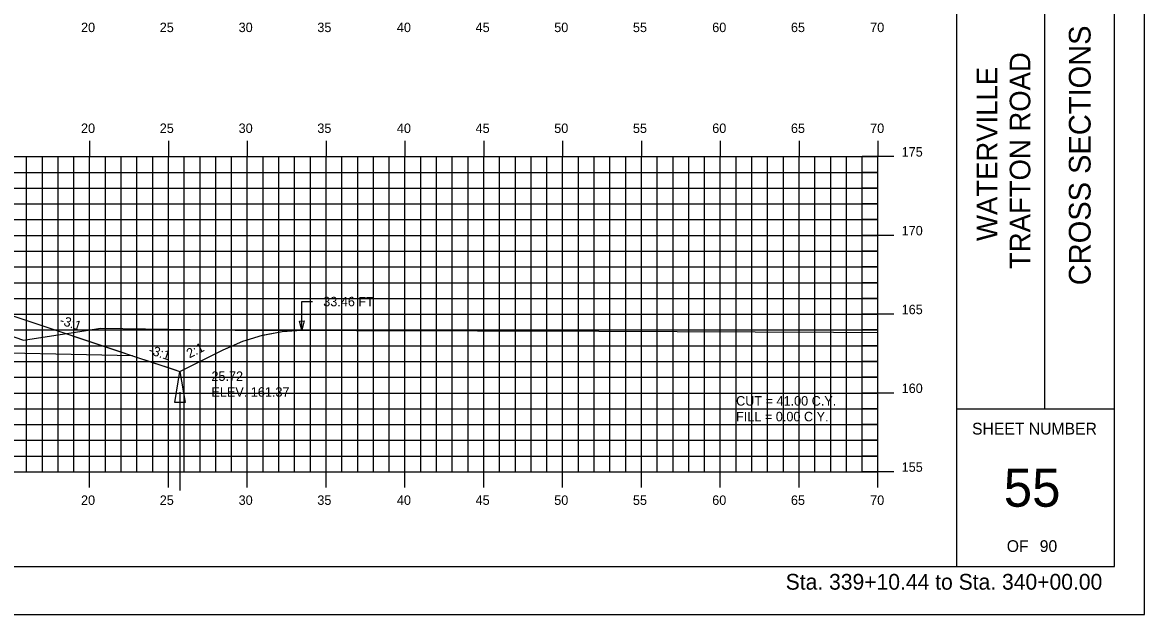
# Model space of a CAD drawing. Extents: x 1142755 to 1142925, y 608981 to 609091.
# Drawn here: x 1142853.5 to 1142924.7, y 608981.3 to 609018.8 of the extents above; entities that cross this region are included whole.
import ezdxf

# ---------------------------------------------------------------- set-up
doc = ezdxf.new("R2010")
doc.units = 0
for name, color, linetype in [('ANNOTATION', 7, 'Continuous'), ('BORDER', 7, 'Continuous'), ('D_Drainage_Ditch_Line', 7, 'Continuous'), ('D_Roadway_SlopeLines', 7, 'Continuous'), ('D_Roadway_SubGrade', 7, 'Continuous'), ('D_Text_Standard', 7, 'Continuous'), ('H_V ANNOTATION', 7, 'Continuous'), ('HIGHWAY_TITLE', 7, 'Continuous'), ('MAJOR', 7, 'Continuous'), ('MINOR', 7, 'Continuous'), ('PLOT BOUNDARY', 7, 'Continuous'), ('S_Roadway_Centerline', 7, 'Continuous')]:
    doc.layers.add(name, color=color, linetype=linetype)

msp = doc.modelspace()

# ---------------------------------------------------------------- linework, layer by layer
msp.add_lwpolyline([(1142852.81, 609000.277), (1142859.606, 608998.012), (1142860.533, 608997.703), (1142863.173, 608996.823), (1142863.533, 608996.703), (1142863.862, 608996.867), (1142866.272, 608998.072), (1142866.422, 608998.137), (1142867.522, 608998.618), (1142867.672, 608998.665), (1142868.772, 608999.007), (1142868.922, 608999.035), (1142870.022, 608999.239), (1142870.172, 608999.248), (1142871.272, 608999.314)])
at = {"layer": 'BORDER'}
for p, q in [((1142912.81, 608984.335), (1142912.81, 609089.335)), ((1142918.401, 608994.338), (1142918.401, 609029.338)), ((1142912.81, 608994.338), (1142922.81, 608994.338))]:
    msp.add_line(p, q, dxfattribs=at)
msp.add_lwpolyline([(1142762.81, 608984.335), (1142922.81, 608984.335), (1142922.81, 609089.335), (1142762.81, 609089.335)], close=True, dxfattribs=at)
at = {"layer": 'D_Drainage_Ditch_Line'}
msp.add_line((1142863.534, 608995.39), (1142863.533, 608989.147), dxfattribs=at)
msp.add_lwpolyline([(1142863.862, 608994.734), (1142863.205, 608994.734), (1142863.533, 608996.703)], close=True, dxfattribs=at)
at = {"layer": 'D_Roadway_SlopeLines'}
for points in [[(1142863.533, 608996.703), (1142866.272, 608998.072), (1142867.522, 608998.618), (1142868.772, 608999.007), (1142870.022, 608999.239), (1142871.272, 608999.314)], [(1142860.533, 608997.703), (1142863.533, 608996.703)]]:
    msp.add_lwpolyline(points, dxfattribs=at)
at = {"layer": 'D_Roadway_SubGrade'}
msp.add_lwpolyline([(1142848.81, 609000.021), (1142848.81, 609000.187), (1142852.81, 609000.027), (1142852.81, 609000.277), (1142852.81, 609000.277), (1142860.533, 608997.703), (1142848.81, 608997.937)], close=True, dxfattribs=at)
at = {"layer": 'D_Text_Standard'}
msp.add_lwpolyline([(1142871.272, 608999.322), (1142871.265, 609001.136), (1142871.945, 609001.136)], dxfattribs=at)
msp.add_lwpolyline([(1142871.272, 608999.322), (1142871.124, 608999.903), (1142871.415, 608999.904)], close=True, dxfattribs=at)
at = {"layer": 'MAJOR'}
for p, q in [((1142857.81, 609011.337), (1142857.81, 609010.335)), ((1142862.81, 609011.337), (1142862.81, 609010.335)), ((1142867.81, 609011.337), (1142867.81, 609010.335)), ((1142872.81, 609011.337), (1142872.81, 609010.335)), ((1142877.81, 609011.337), (1142877.81, 609010.335)), ((1142882.81, 609011.337), (1142882.81, 609010.335)), ((1142887.81, 609011.337), (1142887.81, 609010.335)), ((1142892.81, 609011.337), (1142892.81, 609010.335)), ((1142897.81, 609011.337), (1142897.81, 609010.335)), ((1142902.81, 609011.337), (1142902.81, 609010.335)), ((1142907.81, 609011.337), (1142907.81, 609010.335)), ((1142767.81, 609010.335), (1142907.81, 609010.335)), ((1142767.81, 609010.335), (1142907.81, 609010.335)), ((1142857.81, 608990.335), (1142857.81, 609010.335)), ((1142862.81, 608990.335), (1142862.81, 609010.335)), ((1142867.81, 608990.335), (1142867.81, 609010.335)), ((1142872.81, 608990.335), (1142872.81, 609010.335)), ((1142877.81, 608990.335), (1142877.81, 609010.335)), ((1142882.81, 608990.335), (1142882.81, 609010.335)), ((1142887.81, 608990.335), (1142887.81, 609010.335)), ((1142892.81, 608990.335), (1142892.81, 609010.335)), ((1142897.81, 608990.335), (1142897.81, 609010.335)), ((1142902.81, 608990.335), (1142902.81, 609010.335)), ((1142908.812, 609010.335), (1142906.808, 609010.335)), ((1142907.81, 608990.335), (1142907.81, 609010.335)), ((1142907.81, 608990.335), (1142907.81, 609010.335)), ((1142767.81, 609005.335), (1142907.81, 609005.335)), ((1142908.812, 609005.335), (1142906.808, 609005.335)), ((1142767.81, 609000.335), (1142907.81, 609000.335)), ((1142908.812, 609000.335), (1142906.808, 609000.335)), ((1142767.81, 608995.335), (1142907.81, 608995.335)), ((1142908.812, 608995.335), (1142906.808, 608995.335)), ((1142767.81, 608990.335), (1142907.81, 608990.335)), ((1142767.81, 608990.335), (1142907.81, 608990.335)), ((1142857.81, 608989.333), (1142857.81, 608990.335)), ((1142862.81, 608989.333), (1142862.81, 608990.335)), ((1142867.81, 608989.333), (1142867.81, 608990.335)), ((1142872.81, 608989.333), (1142872.81, 608990.335)), ((1142877.81, 608989.333), (1142877.81, 608990.335)), ((1142882.81, 608989.333), (1142882.81, 608990.335)), ((1142887.81, 608989.333), (1142887.81, 608990.335)), ((1142892.81, 608989.333), (1142892.81, 608990.335)), ((1142897.81, 608989.333), (1142897.81, 608990.335)), ((1142902.81, 608989.333), (1142902.81, 608990.335)), ((1142908.812, 608990.335), (1142906.808, 608990.335)), ((1142907.81, 608989.333), (1142907.81, 608990.335))]:
    msp.add_line(p, q, dxfattribs=at)
at = {"layer": 'MINOR'}
for p, q in [((1142853.81, 608990.335), (1142853.81, 609010.335)), ((1142854.81, 608990.335), (1142854.81, 609010.335)), ((1142855.81, 608990.335), (1142855.81, 609010.335)), ((1142856.81, 608990.335), (1142856.81, 609010.335)), ((1142858.81, 608990.335), (1142858.81, 609010.335)), ((1142859.81, 608990.335), (1142859.81, 609010.335)), ((1142860.81, 608990.335), (1142860.81, 609010.335)), ((1142861.81, 608990.335), (1142861.81, 609010.335)), ((1142863.81, 608990.335), (1142863.81, 609010.335)), ((1142864.81, 608990.335), (1142864.81, 609010.335)), ((1142865.81, 608990.335), (1142865.81, 609010.335)), ((1142866.81, 608990.335), (1142866.81, 609010.335)), ((1142868.81, 608990.335), (1142868.81, 609010.335)), ((1142869.81, 608990.335), (1142869.81, 609010.335)), ((1142870.81, 608990.335), (1142870.81, 609010.335)), ((1142871.81, 608990.335), (1142871.81, 609010.335)), ((1142873.81, 608990.335), (1142873.81, 609010.335)), ((1142874.81, 608990.335), (1142874.81, 609010.335)), ((1142875.81, 608990.335), (1142875.81, 609010.335)), ((1142876.81, 608990.335), (1142876.81, 609010.335)), ((1142878.81, 608990.335), (1142878.81, 609010.335)), ((1142879.81, 608990.335), (1142879.81, 609010.335)), ((1142880.81, 608990.335), (1142880.81, 609010.335)), ((1142881.81, 608990.335), (1142881.81, 609010.335)), ((1142883.81, 608990.335), (1142883.81, 609010.335)), ((1142884.81, 608990.335), (1142884.81, 609010.335)), ((1142885.81, 608990.335), (1142885.81, 609010.335)), ((1142886.81, 608990.335), (1142886.81, 609010.335)), ((1142888.81, 608990.335), (1142888.81, 609010.335)), ((1142889.81, 608990.335), (1142889.81, 609010.335)), ((1142890.81, 608990.335), (1142890.81, 609010.335)), ((1142891.81, 608990.335), (1142891.81, 609010.335)), ((1142893.81, 608990.335), (1142893.81, 609010.335)), ((1142894.81, 608990.335), (1142894.81, 609010.335)), ((1142895.81, 608990.335), (1142895.81, 609010.335)), ((1142896.81, 608990.335), (1142896.81, 609010.335)), ((1142898.81, 608990.335), (1142898.81, 609010.335)), ((1142899.81, 608990.335), (1142899.81, 609010.335)), ((1142900.81, 608990.335), (1142900.81, 609010.335)), ((1142901.81, 608990.335), (1142901.81, 609010.335)), ((1142903.81, 608990.335), (1142903.81, 609010.335)), ((1142904.81, 608990.335), (1142904.81, 609010.335)), ((1142905.81, 608990.335), (1142905.81, 609010.335)), ((1142906.81, 608990.335), (1142906.81, 609010.335)), ((1142767.81, 609009.335), (1142907.81, 609009.335)), ((1142907.81, 609009.335), (1142906.808, 609009.335)), ((1142767.81, 609008.335), (1142907.81, 609008.335)), ((1142907.81, 609008.335), (1142906.808, 609008.335)), ((1142767.81, 609007.335), (1142907.81, 609007.335)), ((1142907.81, 609007.335), (1142906.808, 609007.335)), ((1142767.81, 609006.335), (1142907.81, 609006.335)), ((1142907.81, 609006.335), (1142906.808, 609006.335)), ((1142767.81, 609004.335), (1142907.81, 609004.335)), ((1142907.81, 609004.335), (1142906.808, 609004.335)), ((1142767.81, 609003.335), (1142907.81, 609003.335)), ((1142907.81, 609003.335), (1142906.808, 609003.335)), ((1142767.81, 609002.335), (1142907.81, 609002.335)), ((1142907.81, 609002.335), (1142906.808, 609002.335)), ((1142767.81, 609001.335), (1142907.81, 609001.335)), ((1142907.81, 609001.335), (1142906.808, 609001.335)), ((1142767.81, 608999.335), (1142907.81, 608999.335)), ((1142907.81, 608999.335), (1142906.808, 608999.335)), ((1142767.81, 608998.335), (1142907.81, 608998.335)), ((1142907.81, 608998.335), (1142906.808, 608998.335)), ((1142767.81, 608997.335), (1142907.81, 608997.335)), ((1142907.81, 608997.335), (1142906.808, 608997.335)), ((1142767.81, 608996.335), (1142907.81, 608996.335)), ((1142907.81, 608996.335), (1142906.808, 608996.335)), ((1142767.81, 608994.335), (1142907.81, 608994.335)), ((1142907.81, 608994.335), (1142906.808, 608994.335)), ((1142767.81, 608993.335), (1142907.81, 608993.335)), ((1142907.81, 608993.335), (1142906.808, 608993.335)), ((1142767.81, 608992.335), (1142907.81, 608992.335)), ((1142907.81, 608992.335), (1142906.808, 608992.335)), ((1142767.81, 608991.335), (1142907.81, 608991.335)), ((1142907.81, 608991.335), (1142906.808, 608991.335))]:
    msp.add_line(p, q, dxfattribs=at)
at = {"layer": 'PLOT BOUNDARY'}
msp.add_lwpolyline([(1142754.717, 608981.276), (1142924.717, 608981.276), (1142924.717, 609091.276), (1142754.717, 609091.276)], close=True, dxfattribs=at)
at = {"layer": 'S_Roadway_Centerline'}
msp.add_lwpolyline([(1142851.828, 608999.305), (1142853.607, 608998.697), (1142857.594, 608999.293), (1142858.508, 608999.441), (1142867.036, 608999.327), (1142890.098, 608999.255), (1142904.984, 608999.193), (1142907.81, 608999.178)], dxfattribs=at)

# ---------------------------------------------------------------- texts
at = {"layer": 'ANNOTATION'}
for s, rotation, p in [('-3:1', 341.56528, (1142855.858, 608999.715)), ('-3:1', 341.56505, (1142861.503, 608997.834)), ('2:1', 26.56505, (1142864.139, 608997.524))]:
    msp.add_text(s, height=0.6, rotation=rotation, dxfattribs=at).set_placement(p)
at = {"layer": 'BORDER'}
msp.add_text('CROSS SECTIONS', height=1.37787, rotation=90, dxfattribs=at).set_placement((1142921.295, 609002.172))
for s, height, p in [('SHEET NUMBER', 0.74527, (1142913.776, 608992.701)), ('55', 2.4194, (1142915.786, 608988.118)), ('OF', 0.7453, (1142915.977, 608985.248)), ('90', 0.7453, (1142918.067, 608985.248))]:
    msp.add_text(s, height=height, dxfattribs=at).set_placement(p)
at = {"layer": 'D_Text_Standard'}
for s, p in [('33.46 FT', (1142872.625, 609000.836)), ('25.72', (1142865.534, 608996.103)), ('ELEV. 161.37', (1142865.534, 608995.101)), ('CUT = 41.00 C.Y.', (1142898.81, 608994.535)), ('FILL = 0.00 C.Y.', (1142898.81, 608993.539))]:
    msp.add_text(s, height=0.6, dxfattribs=at).set_placement(p)
at = {"layer": 'H_V ANNOTATION'}
for s, height, p in [('20', 0.6, (1142857.264, 609018.235)), ('25', 0.6, (1142862.256, 609018.235)), ('30', 0.6, (1142867.259, 609018.235)), ('35', 0.6, (1142872.251, 609018.235)), ('40', 0.6, (1142877.296, 609018.235)), ('45', 0.6, (1142882.288, 609018.235)), ('50', 0.6, (1142887.275, 609018.235)), ('55', 0.6, (1142892.267, 609018.235)), ('60', 0.6, (1142897.296, 609018.235)), ('65', 0.6, (1142902.288, 609018.235)), ('70', 0.6, (1142907.312, 609018.235)), ('20', 0.6, (1142857.264, 609011.835)), ('25', 0.6, (1142862.256, 609011.835)), ('30', 0.6, (1142867.259, 609011.835)), ('35', 0.6, (1142872.251, 609011.835)), ('40', 0.6, (1142877.296, 609011.835)), ('45', 0.6, (1142882.288, 609011.835)), ('50', 0.6, (1142887.275, 609011.835)), ('55', 0.6, (1142892.267, 609011.835)), ('60', 0.6, (1142897.296, 609011.835)), ('65', 0.6, (1142902.288, 609011.835)), ('70', 0.6, (1142907.312, 609011.835)), ('175', 0.6, (1142909.31, 609010.335)), ('170', 0.6, (1142909.31, 609005.335)), ('165', 0.6, (1142909.31, 609000.335)), ('160', 0.6, (1142909.31, 608995.335)), ('155', 0.6, (1142909.31, 608990.335)), ('20', 0.6, (1142857.264, 608988.235)), ('25', 0.6, (1142862.256, 608988.235)), ('30', 0.6, (1142867.259, 608988.235)), ('35', 0.6, (1142872.251, 608988.235)), ('40', 0.6, (1142877.296, 608988.235)), ('45', 0.6, (1142882.288, 608988.235)), ('50', 0.6, (1142887.275, 608988.235)), ('55', 0.6, (1142892.267, 608988.235)), ('60', 0.6, (1142897.296, 608988.235)), ('65', 0.6, (1142902.288, 608988.235)), ('70', 0.6, (1142907.312, 608988.235)), ('Sta. 339+10.44 to Sta. 340+00.00', 1.0002, (1142901.956, 608982.855))]:
    msp.add_text(s, height=height, dxfattribs=at).set_placement(p)
at = {"layer": 'HIGHWAY_TITLE'}
for s, height, p in [('TRAFTON ROAD', 1.30428, (1142917.47, 609003.201)), ('WATERVILLE', 1.3043, (1142915.383, 609004.98))]:
    msp.add_text(s, height=height, rotation=90, dxfattribs=at).set_placement(p)

doc.saveas('drawing.dxf')
